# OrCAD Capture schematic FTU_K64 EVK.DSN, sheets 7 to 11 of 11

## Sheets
7 PAGE07  USB: size A4
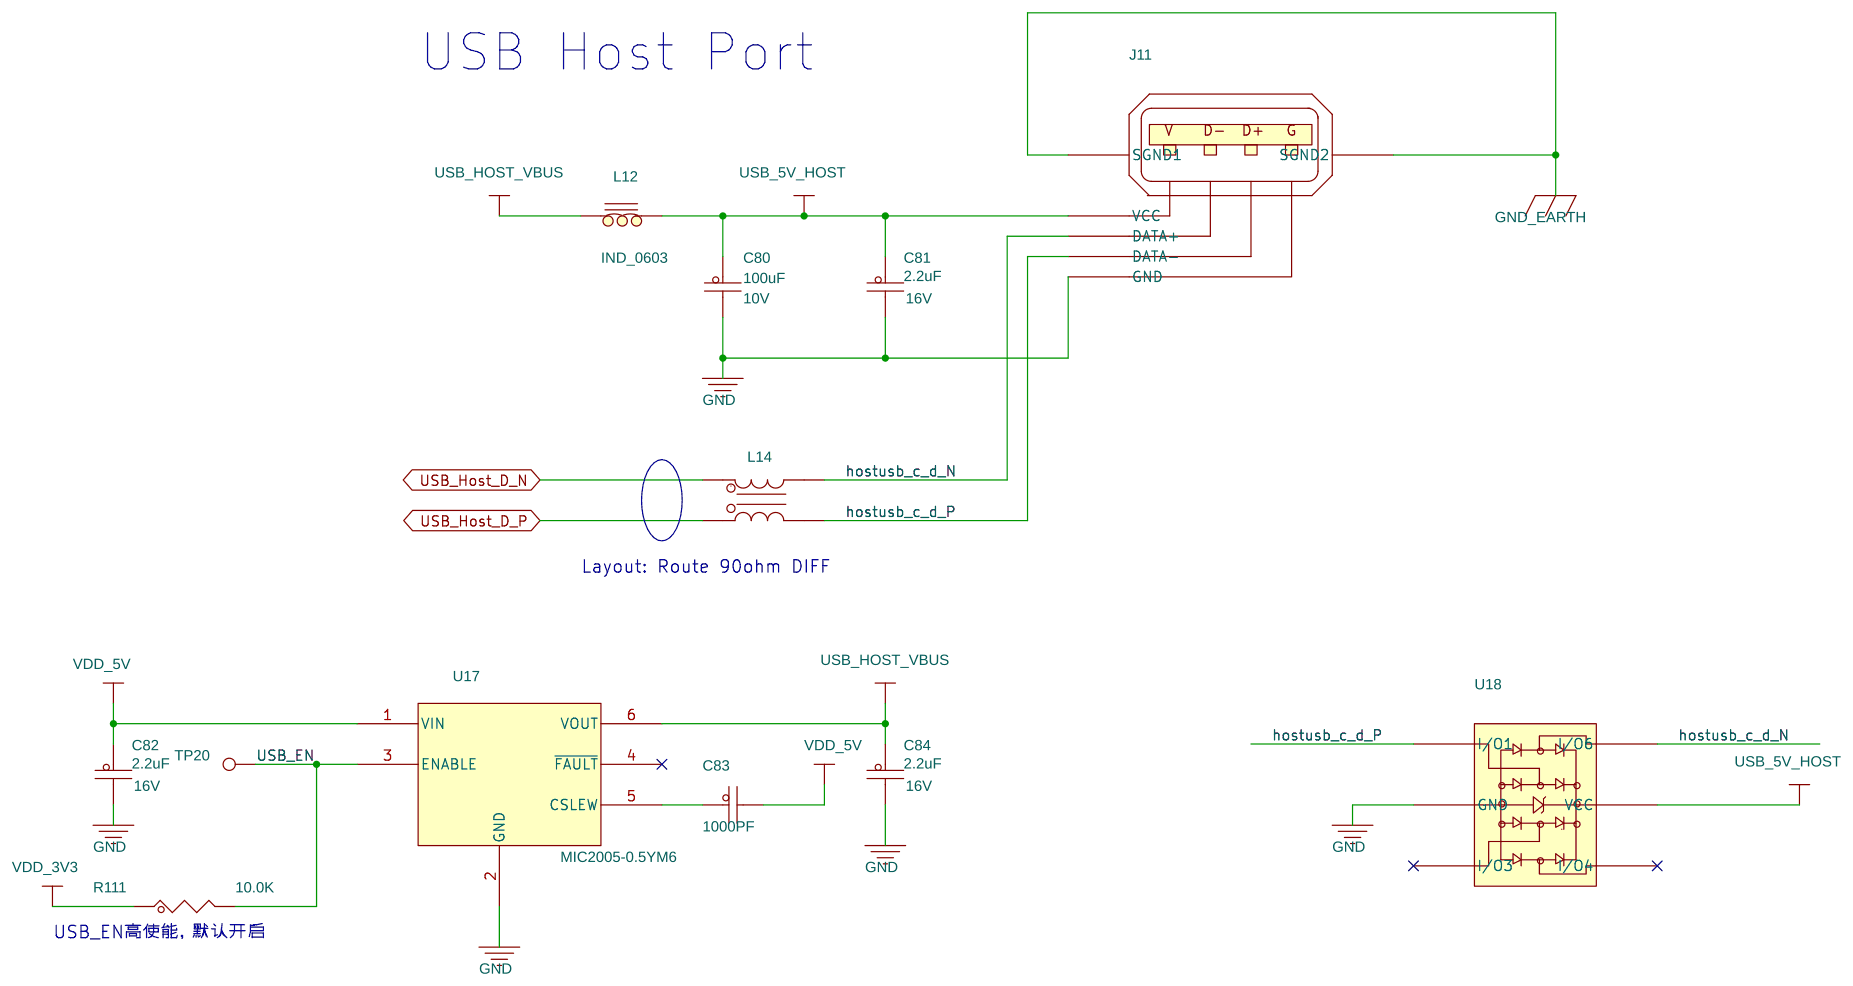
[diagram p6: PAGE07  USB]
8 PAGE08 RS485: size A3
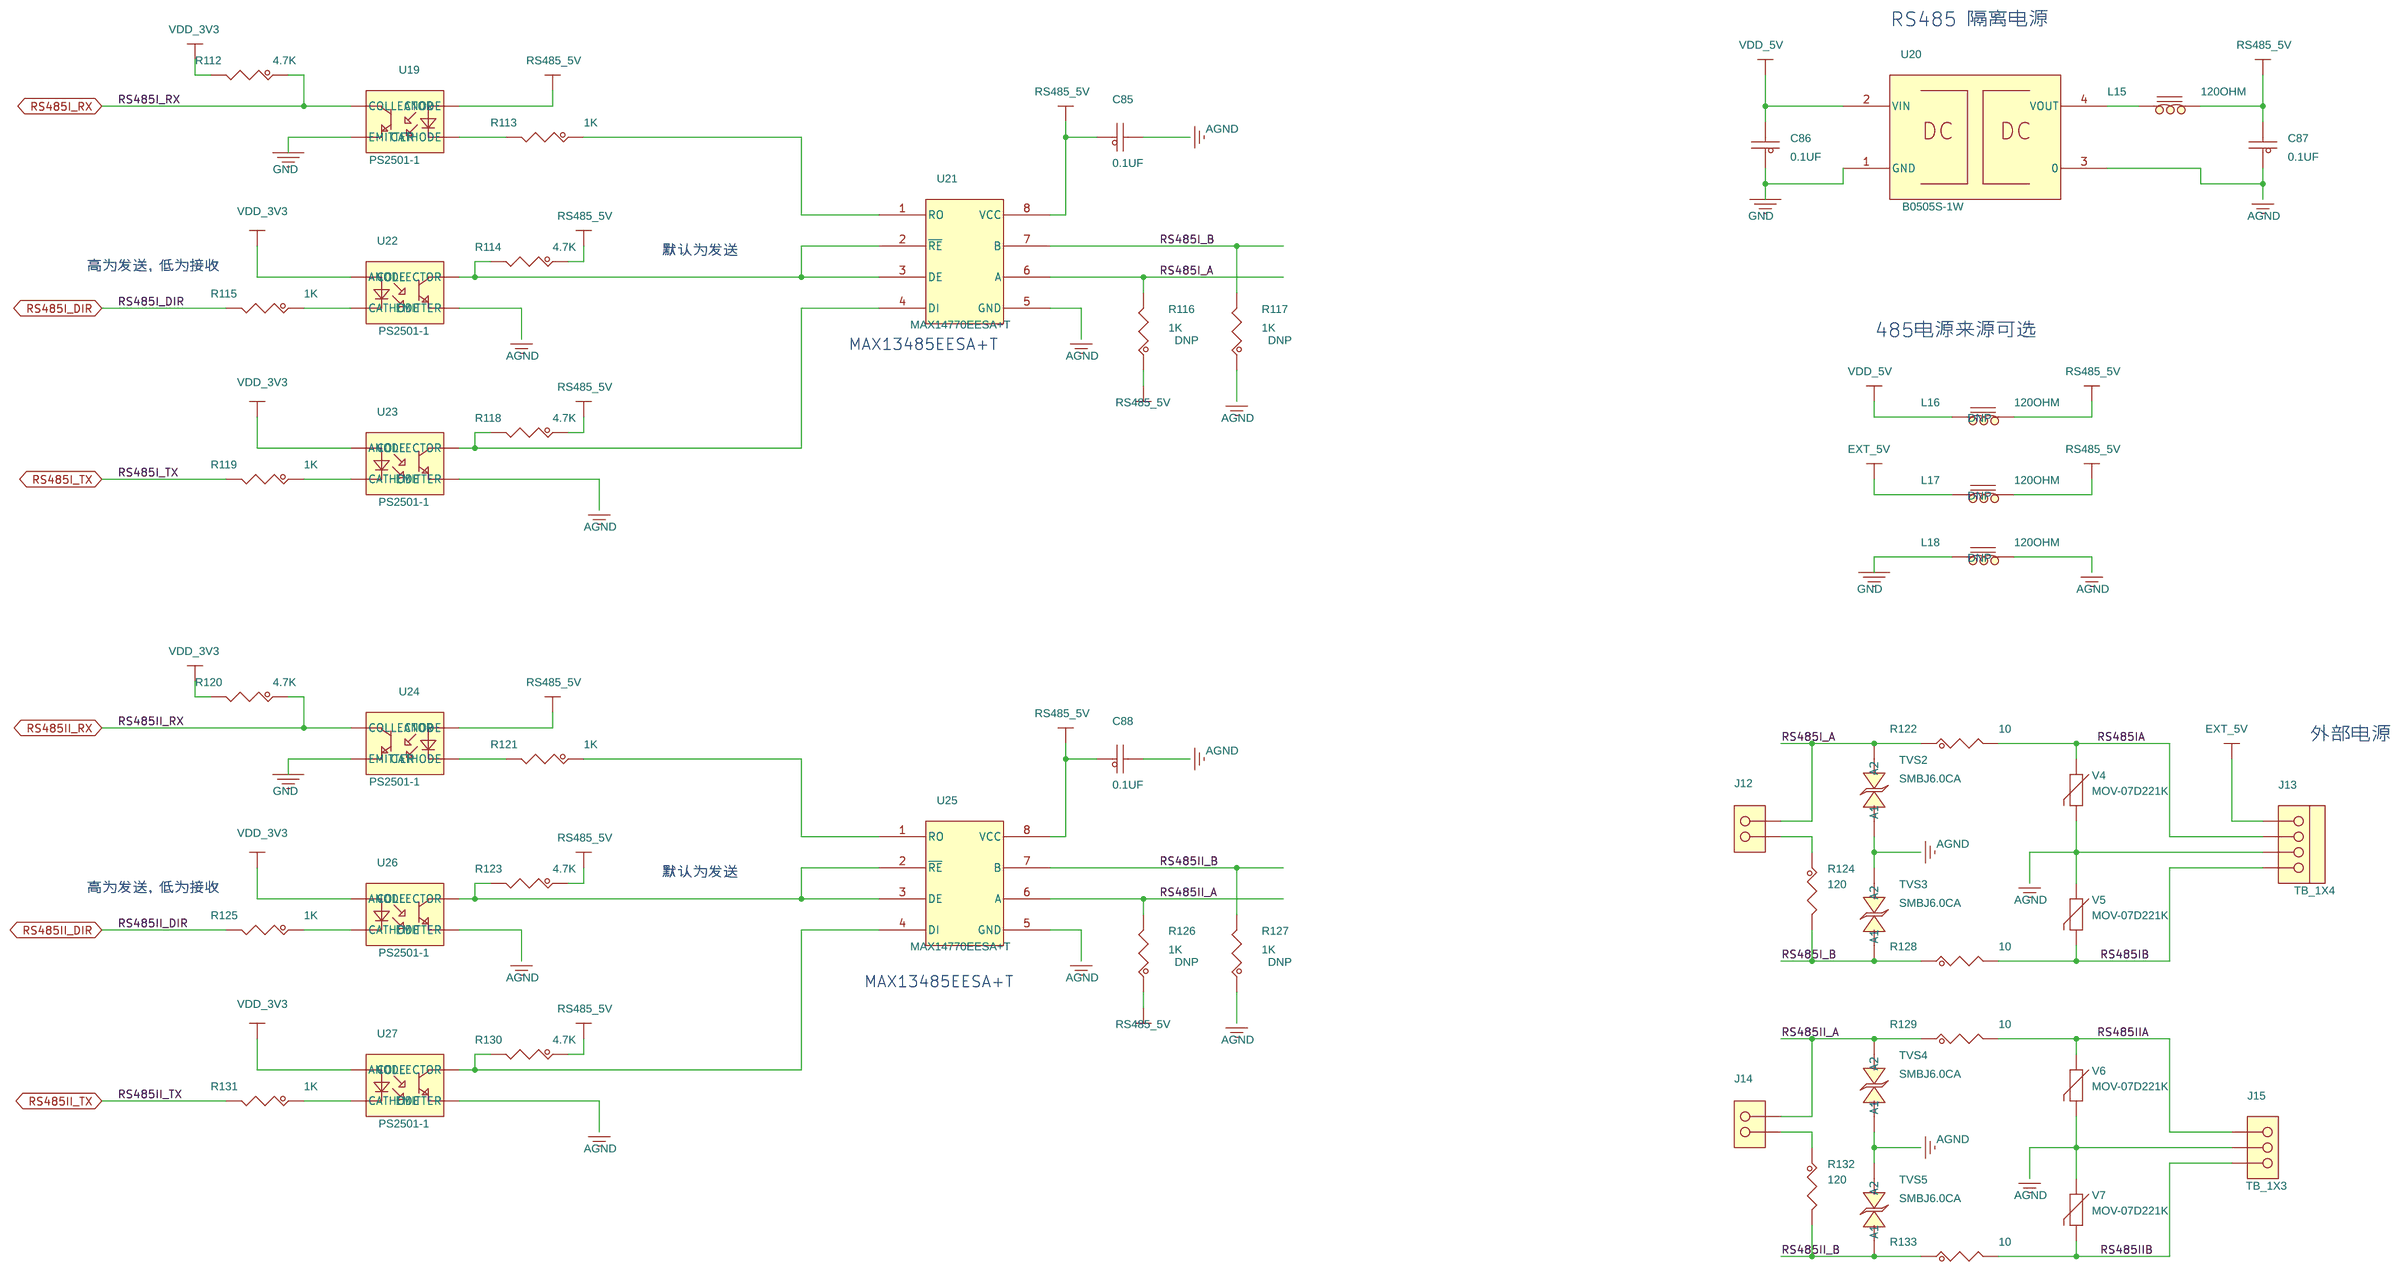
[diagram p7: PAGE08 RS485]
9 PAGE09 WDOG&Debug: size A3
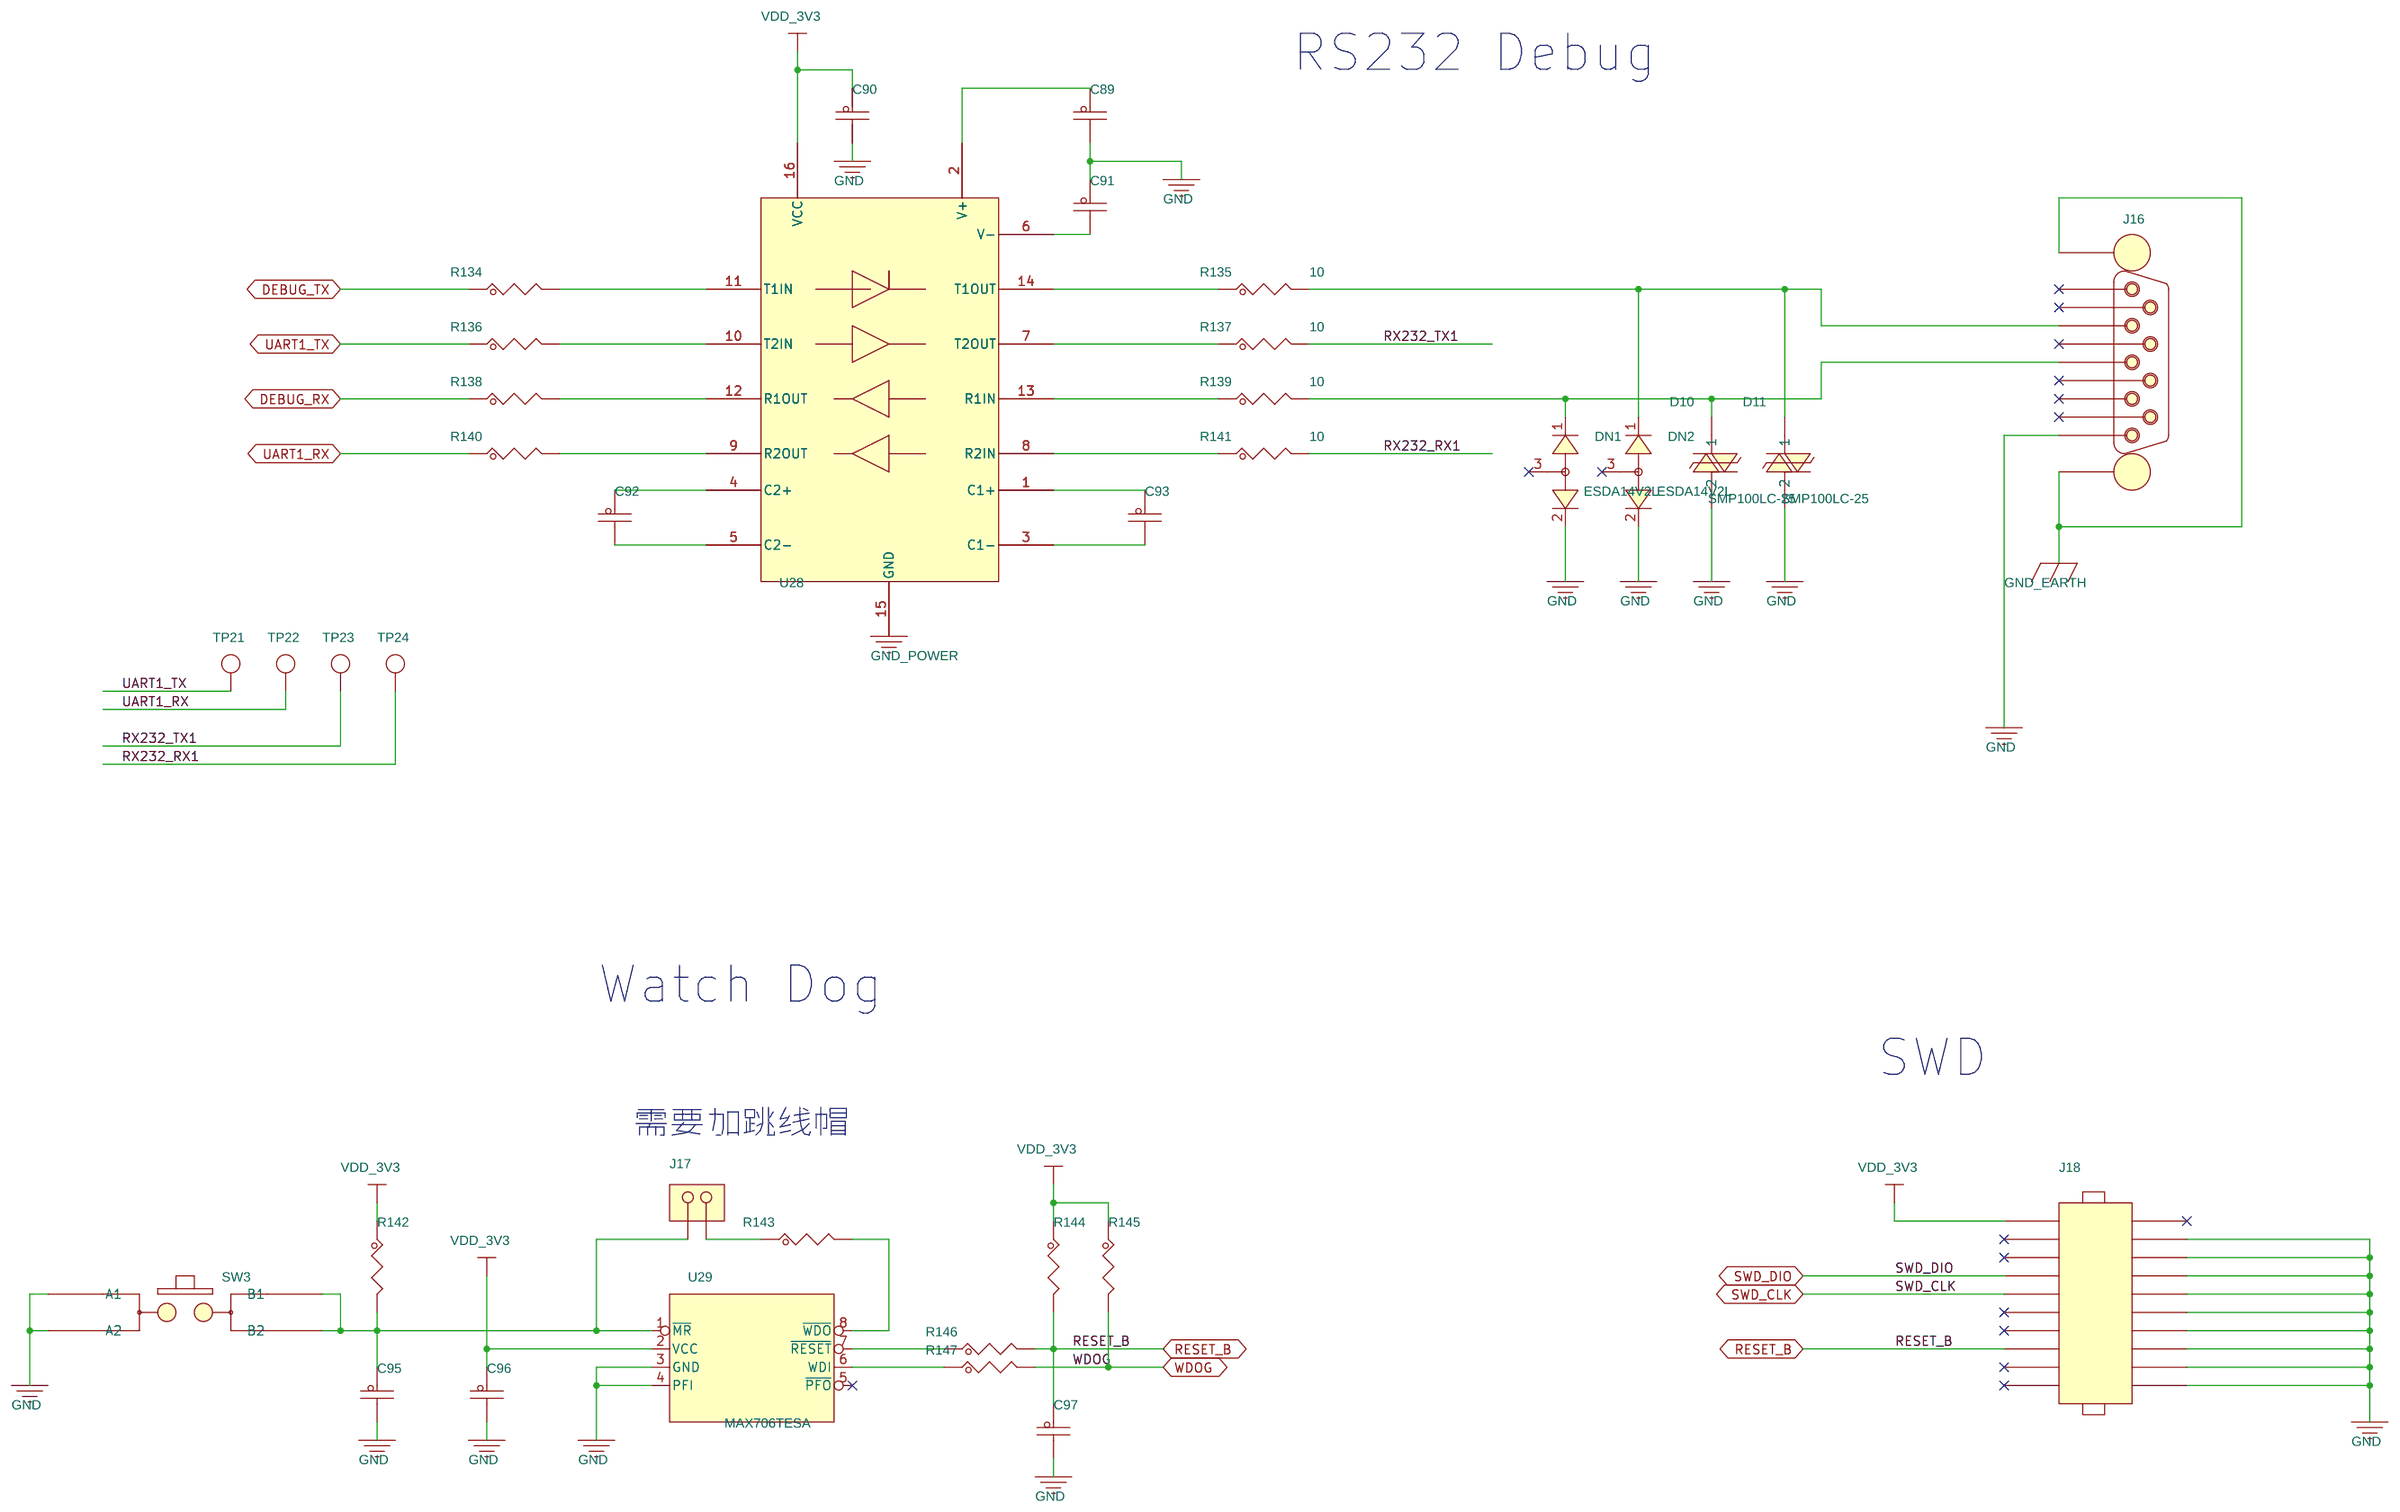
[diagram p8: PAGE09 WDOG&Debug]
10 PAGE10 GPRS&WIFI: size A4
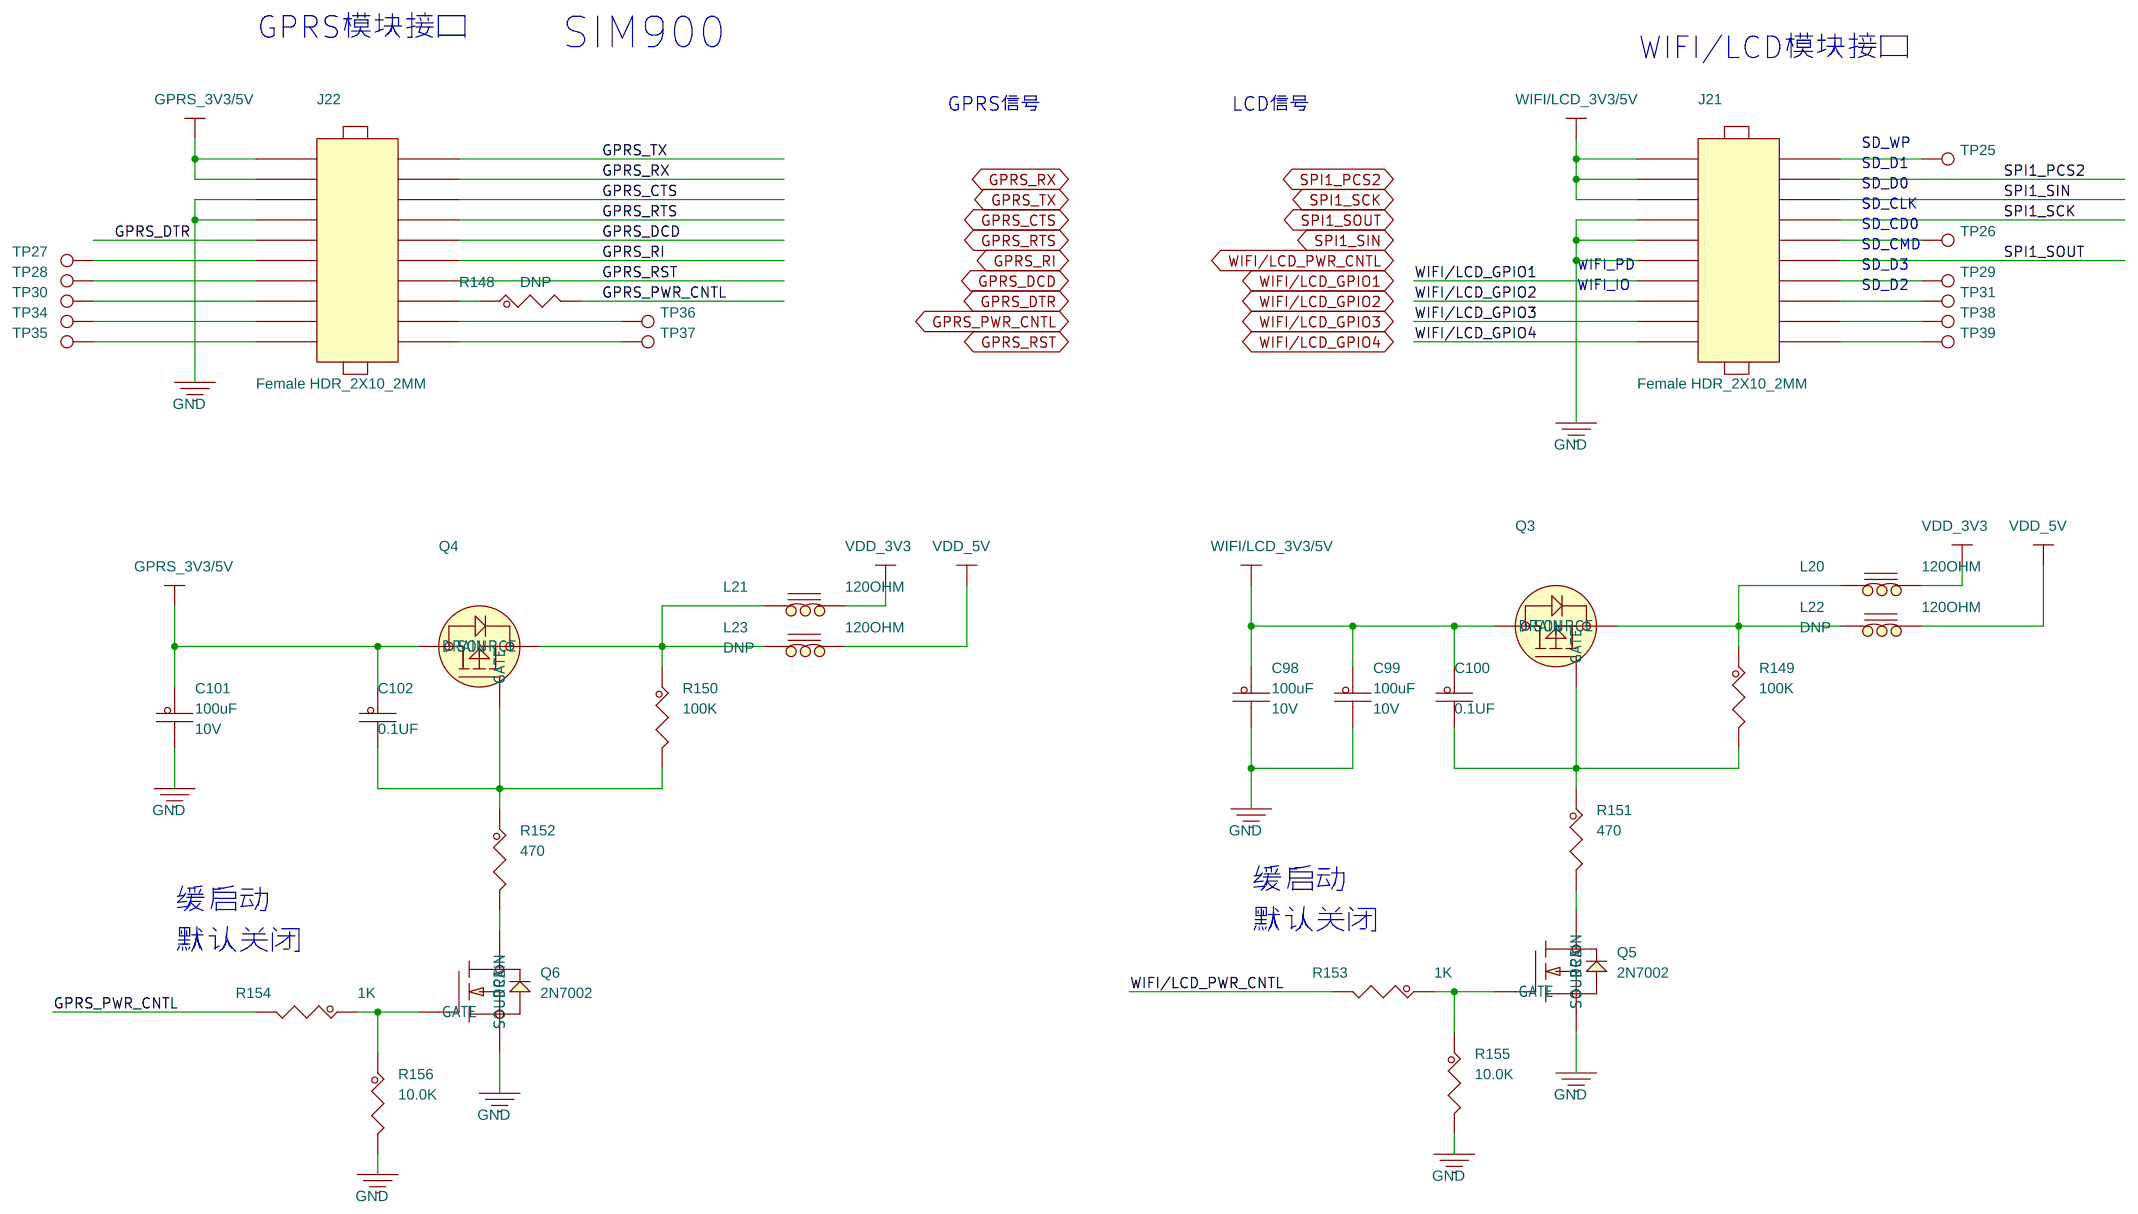
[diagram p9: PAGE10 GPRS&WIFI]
11 PAGE11 Power: size A4
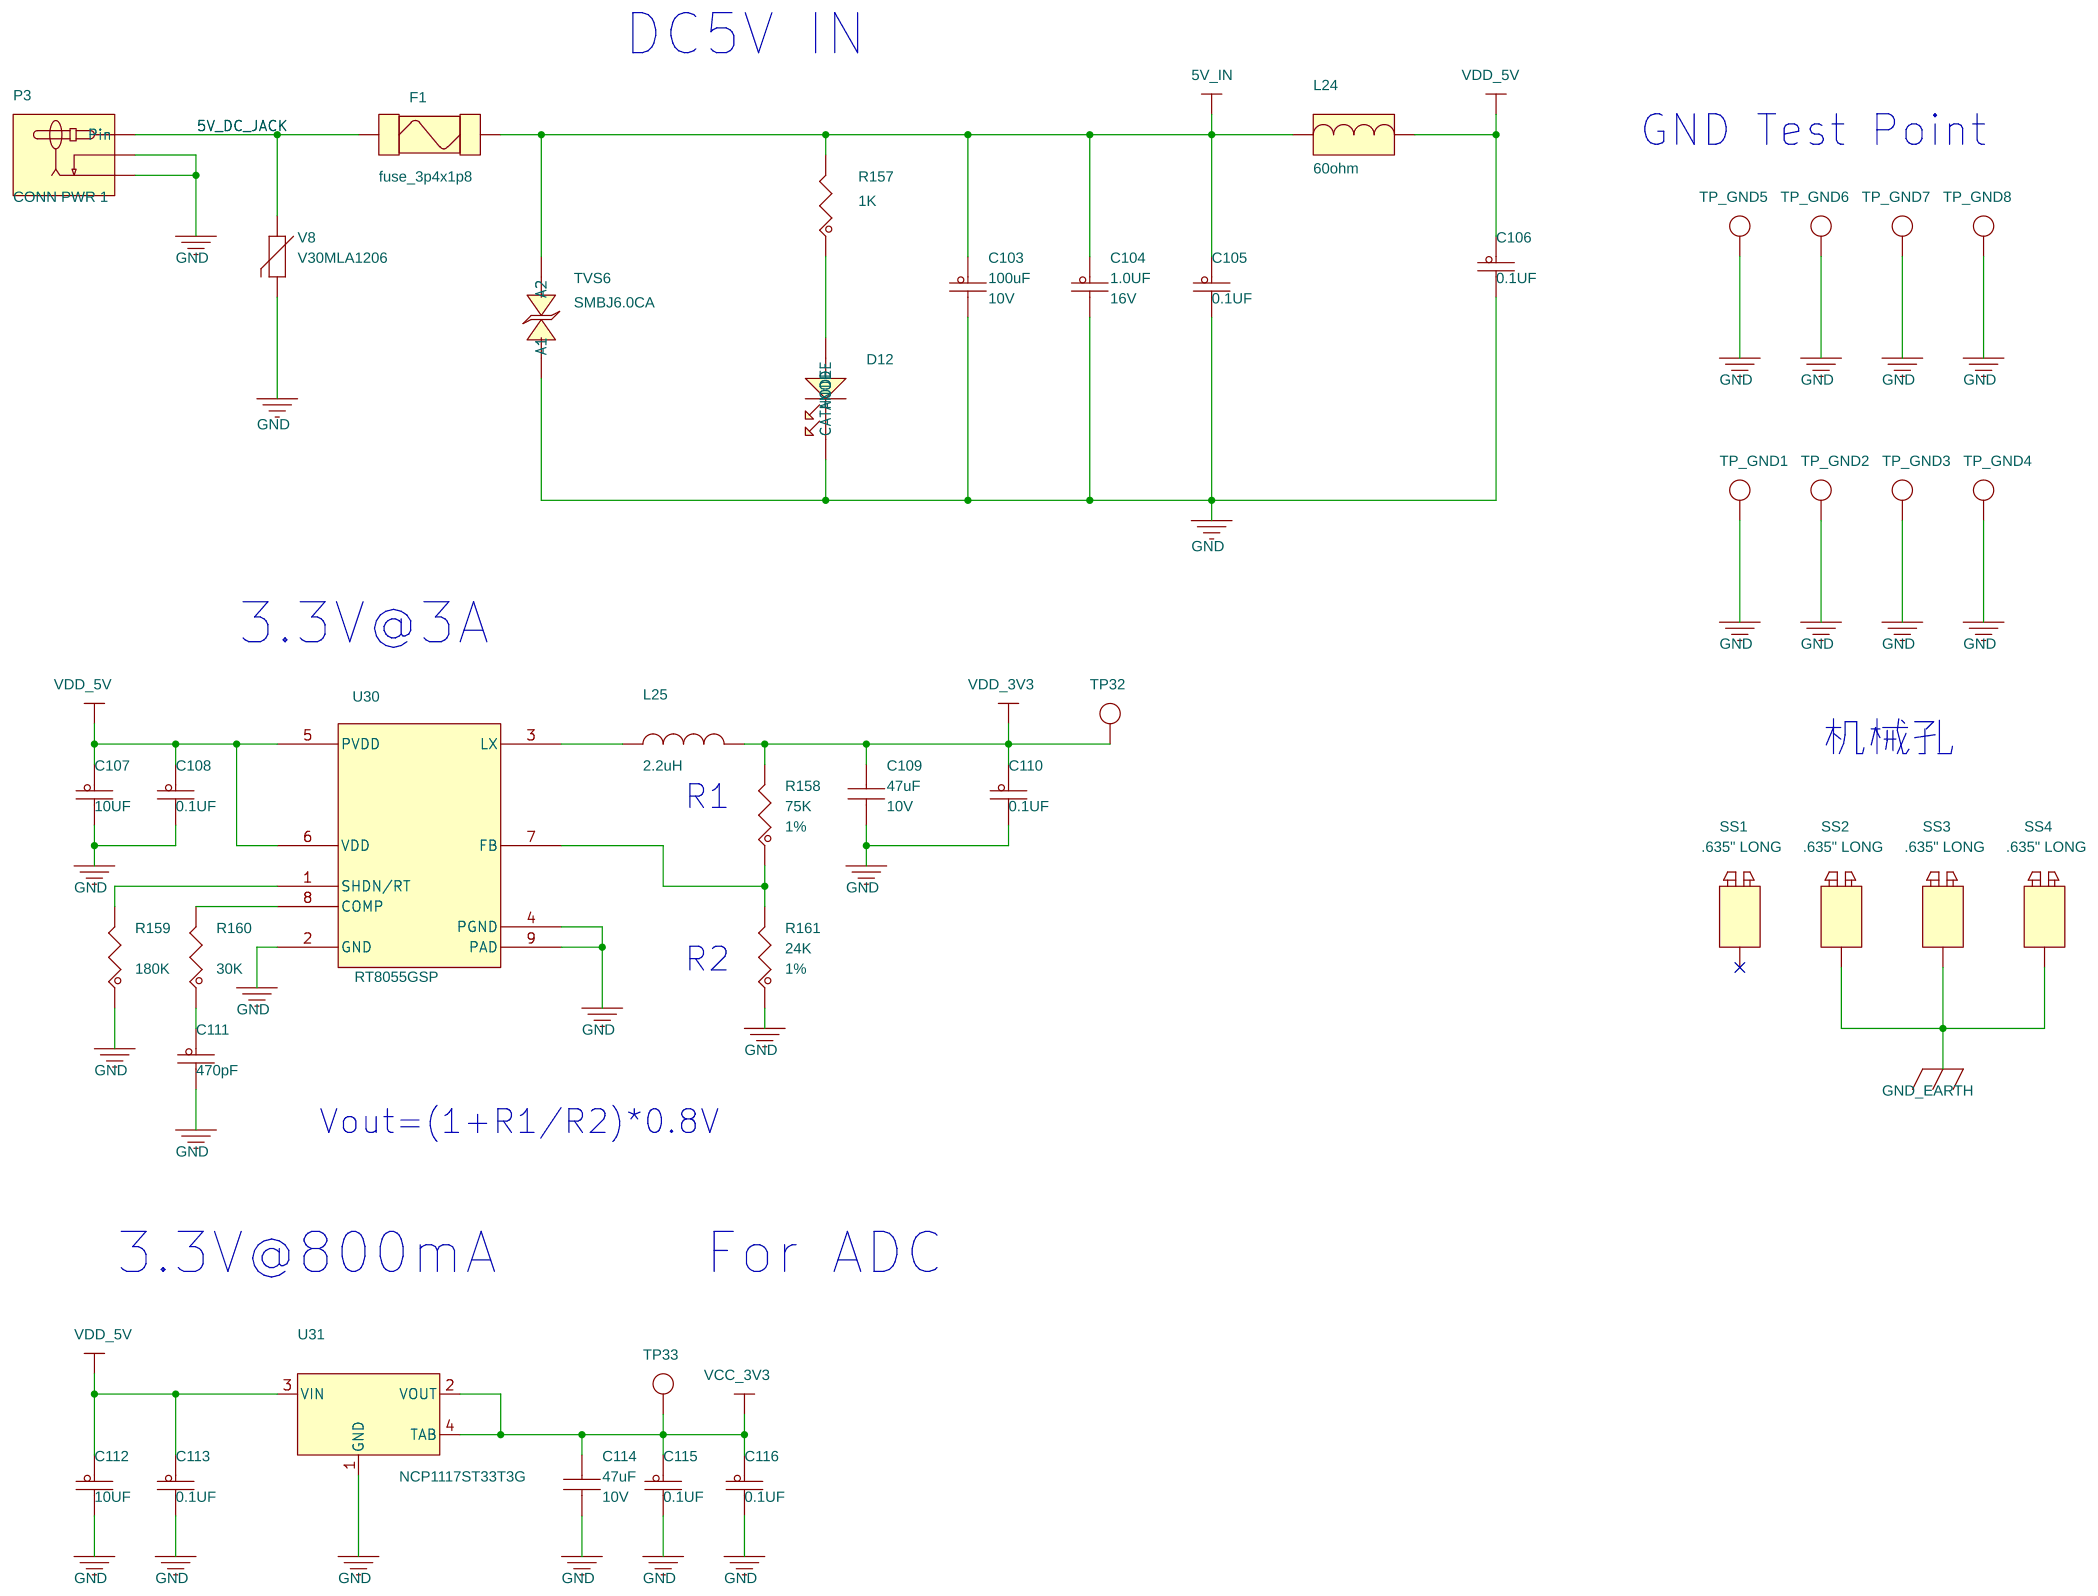
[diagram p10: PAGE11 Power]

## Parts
sheet PAGE07  USB
C80  100uF  [CC1206]
C81  2.2uF  [CC0603]
C82  2.2uF  [CC0603]
C83  1000PF  [CC0603]
C84  2.2uF  [CC0603]
J11  USB_TYPE_A  [USB_A]
L12  120OHM  [IND_0603]
L14  90OHM  [ind4_choke_0805]
R111  10.0K  [RC0603]
TP20  TEST POINT  [C035S]
U17  MIC2005-0.5YM6  [SOT23-6]
U18  SRV05-4  [SOT23-6]
sheet PAGE08 RS485
C85  0.1UF  [CC0603]
C86  0.1UF  [CC0603]
C87  0.1UF  [CC0603]
C88  0.1UF  [CC0603]
J12  HDR 1X2  [hdr102]
J13  TB_1X4  [con4_3p5_14p5x7mm]
J14  HDR 1X2  [hdr102]
J15  TB_1X3  [con3_3p5_11x7mm]
L15  120OHM  [IND_0603]
L16  120OHM  [IND_0603]
L17  120OHM  [IND_0603]
L18  120OHM  [IND_0603]
R112  4.7K  [RC0603]
R113  1K  [RC0603]
R114  4.7K  [RC0603]
R115  1K  [RC0603]
R116  1K  [RC0603]
R117  1K  [RC0603]
R118  4.7K  [RC0603]
R119  1K  [RC0603]
R120  4.7K  [RC0603]
R121  1K  [RC0603]
R122  10  [RC0805]
R123  4.7K  [RC0603]
R124  120  [RC0805]
R125  1K  [RC0603]
R126  1K  [RC0603]
R127  1K  [RC0603]
R128  10  [RC0805]
R129  10  [RC0805]
R130  4.7K  [RC0603]
R131  1K  [RC0603]
R132  120  [RC0805]
R133  10  [RC0805]
TVS2  SMBJ6.0CA  [do-214aa_bidir]
TVS3  SMBJ6.0CA  [do-214aa_bidir]
TVS4  SMBJ6.0CA  [do-214aa_bidir]
TVS5  SMBJ6.0CA  [do-214aa_bidir]
U19  PS2501-1  [4dip300]
U20  B0505S-1W  [B0505S-1W_SIP]
U21  MAX14770EESA+T  [so8_1p27_4x5]
U22  PS2501-1  [4dip300]
U23  PS2501-1  [4dip300]
U24  PS2501-1  [4dip300]
U25  MAX14770EESA+T  [so8_1p27_4x5]
U26  PS2501-1  [4dip300]
U27  PS2501-1  [4dip300]
V4  MOV-07D221K  [varistor_5_9x5p8_th]
V5  MOV-07D221K  [varistor_5_9x5p8_th]
V6  MOV-07D221K  [varistor_5_9x5p8_th]
V7  MOV-07D221K  [varistor_5_9x5p8_th]
sheet PAGE09 WDOG&Debug
C89  0.1UF  [CC0603]
C90  0.1UF  [CC0603]
C91  0.1UF  [CC0603]
C92  0.1UF  [CC0603]
C93  0.1UF  [CC0603]
C95  0.1UF  [CC0603]
C96  0.1UF  [CC0603]
C97  0.1UF  [CC0603]
D10  SMP100LC-25  [DO-214AA]
D11  SMP100LC-25  [DO-214AA]
DN1  ESDA14V2L  [SOT-23]
DN2  ESDA14V2L  [SOT-23]
J16  DB9  [CON_DB9S_RA_318]
J17  HDR 1X2  [hdr102]
J18  HDR 2X10  [HDR_2X10]
R134  0  [RC0603]
R135  10  [RC0805]
R136  0  [RC0603]
R137  10  [RC0805]
R138  0  [RC0603]
R139  10  [RC0805]
R140  0  [RC0603]
R141  10  [RC0805]
R142  10.0K  [RC0603]
R143  0  [RC0603]
R144  10.0K  [RC0603]
R145  10.0K  [RC0603]
R146  0  [RC0603]
R147  0  [RC0603]
SW3  SPST PB  [SW4_PB_ESW_SM_P177]
TP21  TPAD_040  [TPAD_040]
TP22  TPAD_040  [TPAD_040]
TP23  TPAD_040  [TPAD_040]
TP24  TPAD_040  [TPAD_040]
U28  SP3232  [SSOP16]
U29  MAX706TESA  [SO8_1P27_4X5]
sheet PAGE10 GPRS&WIFI
C98  100uF  [CC1206]
C99  100uF  [CC1206]
C100  0.1UF  [CC0603]
C101  100uF  [CC1206]
C102  0.1UF  [CC0603]
J21  Female HDR_2X10_2MM  [HDR210_2MM]
J22  Female HDR_2X10_2MM  [HDR210_2MM]
L20  120OHM  [IND_0603]
L21  120OHM  [IND_0603]
L22  120OHM  [IND_0603]
L23  120OHM  [IND_0603]
Q3  AO3415  [SOT-23]
Q4  AO3415  [SOT-23]
Q5  2N7002  [SOT-23]
Q6  2N7002  [SOT-23]
R148  0  [RC0603]
R149  100K  [RC0603]
R150  100K  [RC0603]
R151  470  [RC0603]
R152  470  [RC0603]
R153  1K  [RC0603]
R154  1K  [RC0603]
R155  10.0K  [RC0603]
R156  10.0K  [RC0603]
TP25  TEST POINT  [C035S]
TP26  TEST POINT  [C035S]
TP27  TEST POINT  [C035S]
TP28  TEST POINT  [C035S]
TP29  TEST POINT  [C035S]
TP30  TEST POINT  [C035S]
TP31  TEST POINT  [C035S]
TP34  TEST POINT  [C035S]
TP35  TEST POINT  [C035S]
TP36  TEST POINT  [C035S]
TP37  TEST POINT  [C035S]
TP38  TEST POINT  [C035S]
TP39  TEST POINT  [C035S]
sheet PAGE11 Power
C103  100uF  [CC1206]
C104  1.0UF  [CC0603]
C105  0.1UF  [CC0603]
C106  0.1UF  [CC0603]
C107  10UF  [CC0805]
C108  0.1UF  [CC0603]
C109  47uF  [CC1206]
C110  0.1UF  [CC0603]
C111  470pF  [CC0603]
C112  10UF  [CC0805]
C113  0.1UF  [CC0603]
C114  47uF  [CC1206]
C115  0.1UF  [CC0603]
C116  0.1UF  [CC0603]
D12  LED_GREEN  [LED_0603]
F1  5A/32V  [fuse_3p4x1p8]
L24  60ohm  [IND_0805]
L25  2.2uH  [ind2_6p3x6p3]
P3  CONN PWR 1  [PJ-202B]
R157  1K  [RC0603]
R158  75K  [RC0603]
R159  180K  [RC0603]
R160  30K  [RC0603]
R161  24K  [RC0603]
SS1  .635" LONG  [spacer_139t]
SS2  .635" LONG  [spacer_139t]
SS3  .635" LONG  [spacer_139t]
SS4  .635" LONG  [spacer_139t]
TP32  TPAD_040  [TPAD_040]
TP33  TPAD_040  [TPAD_040]
TP_GND1  TESTLOOP_BLACK  [tp_th_063]
TP_GND2  TESTLOOP_BLACK  [tp_th_063]
TP_GND3  TESTLOOP_BLACK  [tp_th_063]
TP_GND4  TESTLOOP_BLACK  [tp_th_063]
TP_GND5  TPAD_040  [TPAD_040]
TP_GND6  TPAD_040  [TPAD_040]
TP_GND7  TPAD_040  [TPAD_040]
TP_GND8  TPAD_040  [TPAD_040]
TVS6  SMBJ6.0CA  [do-214aa_bidir]
U30  RT8055GSP  [so8_1p27_4x5_tab]
U31  NCP1117ST33T3G  [sot223]
V8  V30MLA1206  [RC1206]

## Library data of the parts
C80 C98 C99 C101 C103 = CAP_NP: CAP CER 100uF 10V 20% X5R 1206; AGILE_PN: 150-78880; CAD_APPROVED: Yes; FPLIST: CC1206_OV,CC1206,1206_CC; HEIGHT: 1.9MM; MFG_NAME01: TDK; MFG_PN01: C3216X5R1A107M; ROHS: Yes; Tolerance: 20%; VOLTAGE: 10V; WVDC: 10V
C81 C82 C84 = CAP_NP: CAP CER 2.2UF 16V 10% X5R 0603; AGILE_PN: 150-75417; CAD_APPROVED: YES; FPLIST: CC0603_OV,CC0603,0603_CC; HEIGHT: 0.9 MM; MFG_NAME01: MURATA; MFG_PN01: GRM188R61C225KE15D; ROHS: Yes; Tolerance: 10%; VOLTAGE: 16V; voltage rating: 16V
C83 = CAP_NP: CAP CER 1000PF 50V 10% C0G 0603; AGILE_PN: 150-75921; CAD_APPROVED: Yes; FPLIST: CC0603_OV,CC0603,0603_CC; HEIGHT: 0.91MM; MFG_NAME01: AVX; MFG_PN01: 06035U102KAT2A; ROHS: Yes; Tolerance: 10%; VOLTAGE: 50V
J11 = USB_A: CON 1X4 USB_TYPE_A_FEMALE RA SHLD TH -- 276H AU; AGILE_PN: 210-30008; CAD_APPROVED: Yes; HEIGHT: 7.01MM; MFG_NAME01: TYCO ELECTRONICS; MFG_PN01: 292303-1; ROHS: Yes
L12 = BEAD_0: IND FER BEAD 120OHM@100MHZ 2A 25% 0603; AGILE_PN: 180-30008; CAD_APPROVED: Yes; FPLIST: IND_0603,0603_CC; HEIGHT: 0.95MM; MFG_NAME01: MURATA; MFG_PN01: BLM18PG121SH1; PART_TYPE: FERRITE; ROHS: Yes; Tolerance: 25%
L14 = DLW43: IND CHK 90 OHM@100MHZ 330MA 25% 0805; AGILE_PN: 180-76336; CAD_APPROVED: Yes; HEIGHT: 1MM; MFG_NAME01: MURATA; MFG_PN01: DLW21HN900SQ2L; PART_TYPE: CHOKE; ROHS: Yes; Tolerance: 25%
R111 R142 R144 R145 R155 R156 = RES: RES MF 10.0K 1/10W 1% 0603; AGILE_PN: 470-75422; CAD_APPROVED: Yes; FPLIST: RC0603_OV,RC0603,0603_CC; MFG_NAME01: KOA SPEER; MFG_PN01: RK73H1JTTD1002F; ROHS: Yes; Tolerance: 5%
TP20 TP25-TP31 TP34-TP39 = Test_pad: TEST POINT PAD 35 MIL SMT, NO PART TO ORDER; AGILE_PN: 280-75148; ASSY_OPT: DNP; CAD_APPROVED: Yes; HEIGHT: 0.1 MM; MFG_NAME01: NA; MFG_PN01: NA; ROHS: Yes
U17 = MIC2015-0.5YM6: IC LIN SW PWR 0.5A 2.5-5.5V SOT23-6; AGILE_PN: 315-78290; CAD_APPROVED: Yes; HEIGHT: 1.45 MM; MFG_NAME01: MICREL; ROHS: Yes
U18 = SRV05-4: DIODE TVS ARRAY 12A 5V 300W SOT23_S6; AGILE_PN: 480-75205; CAD_APPROVED: Yes; HEIGHT: 1.45mm; MFG_NAME01: SEMTECH CORP; MFG_PN01: SRV05-4.TCT; ROHS: Yes
C85-C88 C100 C102 C105 C106 C108 C110 C113 C115 C116 = CAP_NP: CAP CER 0.10UF 25V 10% X7R 0603; AGILE_PN: 150-75016; CAD_APPROVED: Yes; FPLIST: CC0603_OV,CC0603,0603_CC; HEIGHT: 0.97 MM; MFG_NAME01: KEMET; MFG_PN01: C0603C104K3RAC; ROHS: Yes; Tolerance: 10%; VOLTAGE: 25V
J12 J14 J17 = CONN_HDR_2X1: HDR 1X2 TH 100MIL SP 330H SN 120L; AGILE_PN: 210-79561; CAD_APPROVED: Yes; HEIGHT: 8.39MM; MFG_NAME01: FRAMATOME CONNECTORS INTERNATIONAL; MFG_PN01: 69190-402HLF; ROHS: Yes
J13 = CON_HDR_1X4: CON 1X4 TB TH 3.5MM SP 335H -- 138L; AGILE_PN: 210-80422; CAD_APPROVED: Yes; HEIGHT: 8.5MM; MFG_NAME01: Phoenix Contact; MFG_PN01: 1751264; ROHS: Yes
J15 = CONN_HDR_3X1: CON 1X3 TB TH 3.5MM SP 354H -- 118L; AGILE_PN: 210-80378; CAD_APPROVED: Yes; HEIGHT: 9MM; MFG_NAME01: Phoenix Contact; MFG_PN01: 1751251; ROHS: Yes
L15 L20 L21 = BEAD_0: IND FER BEAD 120OHM@100MHZ 2A 25% 0603; AGILE_PN: 180-30008; CAD_APPROVED: Yes; FPLIST: IND_0603,0603_CC; HEIGHT: 0.95MM; MFG_NAME01: MURATA; MFG_PN01: BLM18PG121SH1; PART_TYPE: FERRITE; PRIORITY_PN: 024-00067; ROHS: Yes; ROOM: RMII_PHY; Tolerance: 25%
L16-L18 L22 L23 = BEAD_0: IND FER BEAD 120OHM@100MHZ 2A 25% 0603; AGILE_PN: 180-30008; ASSY_OPT: DNP; CAD_APPROVED: Yes; FPLIST: IND_0603,0603_CC; HEIGHT: 0.95MM; MFG_NAME01: MURATA; MFG_PN01: BLM18PG121SH1; PART_TYPE: FERRITE; PRIORITY_PN: 024-00067; ROHS: Yes; ROOM: RMII_PHY; Tolerance: 25%
R112-R115 R118-R121 R123 R125 R130 R131 R153 R154 = RES: RES MF 10K 1/10W 5% 0603; AGILE_PN: 470-75410; CAD_APPROVED: Yes; FPLIST: RC0603_OV,RC0603,0603_CC; MFG_NAME01: KOA SPEER; MFG_PN01: RK73B1JTTD103J; ROHS: Yes; Tolerance: 5%
R116 R117 R126 R127 = RES: RES MF 10K 1/10W 5% 0603; AGILE_PN: 470-75410; ASSY_OPT: DNP; CAD_APPROVED: Yes; FPLIST: RC0603_OV,RC0603,0603_CC; MFG_NAME01: KOA SPEER; MFG_PN01: RK73B1JTTD103J; ROHS: Yes; Tolerance: 5%
R122 R128 R129 R133 = RES: RES MF 10 OHM 1/2W 5% 1210; AGILE_PN: 470-76662; CAD_APPROVED: Yes; FPLIST: RC1210,1210_CC; MFG_NAME01: KOA SPEER; MFG_PN01: RK73B2ETTE100J; ROHS: Yes; Tolerance: 5%
R124 R132 = RES: RES MF 120 OHM 1/8W 5% 0805; AGILE_PN: 470-30428; CAD_APPROVED: Yes; FPLIST: RC0805_OV,RC0805,0805_CC; MFG_NAME01: KOA SPEER; MFG_PN01: RK73B2ATTD121J; ROHS: Yes; Tolerance: 5%
TVS2 TVS5 = DIODE_TVS_BIDIR: DIODE TVS BIDIR 6.0V600W DO-214AB; AGILE_PN: 480-78509; CAD_APPROVED: Yes; HEIGHT: 2.62MM; MFG_NAME01: LITTELFUSE; ROHS: Yes
TVS3 TVS4 = DIODE_TVS_BIDIR: DIODE TVS BIDIR 13V 1500W DO-214AB; AGILE_PN: 480-78509; CAD_APPROVED: Yes; HEIGHT: 2.62MM; MFG_NAME01: LITTELFUSE; ROHS: Yes
U19 U22-U24 U26 U27 = PHOTOCOUPLER_4P: TRAN NPN PHOTOCOUPLER 80MA 80V DIP4; AGILE_PN: 480-78489; CAD_APPROVED: Yes; HEIGHT: 4.55MM; MFG_NAME01: CEL; ROHS: Yes
U20 = B0505S-1W: CLASS: IC; MFG_NAME01: MORNSUN
U21 = MAX13485: IC RS485 Transciever MAX14770EESA+T/SO8; CLASS: IC; MFG_NAME01: MAXIM; Part Number: S.01.67.01.0199
U25 = MAX13485: IC RS485 Transciever MAX14770EESA+T/SO8; MFG_NAME01: MAXIM; Part Number: S.01.67.01.0199
V4-V7 = VARISTOR: VARISTOR 140V 10% 0.25W RADIAL; AGILE_PN: 470-80124; CAD_APPROVED: Yes; MFG_NAME01: Bourns; ROHS: Yes
C89-C93 C95-C97 = CAP_NP: CAP CER 0.10UF 25V 10% X7R 0603; AGILE_PN: 150-75016; CAD_APPROVED: YES; FPLIST: CC0603_OV,CC0603,0603_CC; HEIGHT: 0.97 MM; MFG_NAME01: KEMET; MFG_PN01: C0603C104K3RAC; ROHS: Yes; Tolerance: 10%; VOLTAGE: 25V
D10 D11 = BTSS-2P_0: TVS; MFG_NAME01: ST
DN1 DN2 = ESDA14V2L: DUAL TRANSIL ARRAY TVS; MFG_NAME01: ST
J16 = CONN_DB9F_MTGTABS: CON 9 DB 0.318 SKT RA SHLD TH 54MIL SP 509H AU; AGILE_PN: 210-75755; CAD_APPROVED: Yes; HEIGHT: 12.92 MM; MFG_NAME01: TYCO ELECTRONICS; MFG_PN01: 5747844-4; ROHS: Yes
J18 = HDR_2X10: HDR 2X10 TH 100MIL CTR 363H AU; AGILE_PN: 210-75841; CAD_APPROVED: Yes; HEIGHT: 9.22MM; MFG_NAME01: TYCO ELECTRONICS; MFG_PN01: 1761602-7; ROHS: Yes
R134 R136 R138 R140 R143 R146 R147 = RES: RES MF ZERO OHM 1/10W -- 0603; AGILE_PN: 470-75407; CAD_APPROVED: Yes; FPLIST: RC0603_OV,RC0603,R603-X2,0603_CC; HEIGHT: 0.55 MM; MFG_NAME01: THYE MING TECH CO LTD; MFG_PN01: CR-03JL7----0R; ROHS: Yes; SIGNAL_MODEL: DEFAULT_RESISTOR_0.001OHM_2_1; Tolerance: 5%
R135 R137 R139 R141 = RES: RES MF 10.0 OHM 1/8W 1% 0805; AGILE_PN: 470-75903; CAD_APPROVED: Yes; FPLIST: RC0805_OV,RC0805,0805_CC; MFG_NAME01: BOURNS; MFG_PN01: CR0805-FX-10R0ELF; ROHS: Yes; Tolerance: 5%
SW3 = SW_PB_ESW: SW SPST MOM NO PB TACT 50mA 50V SMT; AGILE_PN: 510-77562; CAD_APPROVED: Yes; HEIGHT: 5MM; MFG_NAME01: E SWITCH; MFG_PN01: TL3301AF260QG/TR; ROHS: Yes
TP21-TP24 TP32 TP33 TP_GND5-TP_GND8 = TestLoop: TEST POINT PAD 40MIL DIA SMT, NO PART TO ORDER; AGILE_PN: 211-76643; CAD_APPROVED: Yes; HEIGHT: 0.1MM; MFG_NAME01: NOTACOMPONENT; MFG_PN01: NOTACOMPONENT; ROHS: Yes
U28 = SP3232E: IC XCVR RS232 120KBPS 3.0-5.5V SSOP16; AGILE_PN: 312-77064; CAD_APPROVED: Yes; HEIGHT: 1.99MM; MFG_NAME01: SIPEX; MFG_PN01: SP3232ECA-L; ROHS: Yes
U29 = ADM706_8P: IC VSUP MPU VOLTAGE MONITOR -- 1-5.5V SOIC8; AGILE_PN: 312-80124; CAD_APPROVED: Yes; HEIGHT: 1.75MM; MFG_NAME01: MAXIM; ROHS: Yes
J21 J22 = HDR_2X10: MFG_NAME01: PINREX ENTERPRISE CO., LTD
Q3 Q4 = MOSFET_P: TRAN PMOS PWR 12V 4.3A SOT23; AGILE_PN: 480-77718; CAD_APPROVED: Yes; HEIGHT: 1.12MM; MFG_NAME01: AOS; ROHS: Yes
Q5 Q6 = 2N7002: TRAN NMOS 60V 115MA SOT23; AGILE_PN: 480-75159; CAD_APPROVED: Yes; HEIGHT: 1.3MM; MFG_NAME01: ON SEMICONDUCTOR; MFG_PN01: 2N7002LT1G; ROHS: Yes
R148 = RES: RES MF ZERO OHM 1/10W -- 0603; AGILE_PN: 470-75407; ASSY_OPT: DNP; CAD_APPROVED: Yes; FPLIST: RC0603_OV,RC0603,R603-X2,0603_CC; HEIGHT: 0.55 MM; MFG_NAME01: THYE MING TECH CO LTD; MFG_PN01: CR-03JL7----0R; ROHS: Yes; SIGNAL_MODEL: DEFAULT_RESISTOR_0.001OHM_2_1; Tolerance: 5%
R149-R152 = RES: RES MF 470 OHM 1/10W 1% 0603; AGILE_PN: 470-30133; CAD_APPROVED: Yes; FPLIST: RC0603_OV,RC0603,0603_CC; MFG_NAME01: KOA SPEER; MFG_PN01: RK73H1JTTD4700F; ROHS: Yes; Tolerance: 5%
C104 = CAP_NP: CAP CER 1.0UF 16V 10% X7R 0603; AGILE_PN: 150-30124; CAD_APPROVED: Yes; FPLIST: CC0603_OV,CC0603,0603_CC; HEIGHT: 1.0MM; MFG_NAME01: AVX; MFG_PN01: 0603YC105KAT2A; ROHS: Yes; SIGNAL_MODEL: DEFAULT_CAPACITOR_1e+06pF_2_1; Tolerance: 10%; VOLTAGE: 16V; WVDC: 16V
C107 C112 = CAP_NP: CAP CER 10UF 16V 10% X5R 0805; AGILE_PN: 150-75283; CAD_APPROVED: Yes; FPLIST: CC0805_OV,CC0805,0805_CC; HEIGHT: 1.45MM; MFG_NAME01: AVX; MFG_PN01: 0805YD106KAT2A; ROHS: Yes; Tolerance: 10%; VOLTAGE: 16V
C109 C114 = MOT_CAP: CAP CER 47uF 10V 20% X5R 1206; AGILE_PN: 150-78578; CAD_APPROVED: Yes; FPLIST: CC1206_OV,CC1206,1206_CC; HEIGHT: 1.80MM; MFG_NAME01: TAIYO YUDEN; MFG_PN01: LMK316BJ476ML-T; ROHS: Yes; SIGNAL_MODEL: DEFAULT_CAPACITOR_4.7e+07pF_2_1; Tolerance: 20%; VOLTAGE: 10V; WVDC: 10V
C111 = CAP_NP: CAP CER 470PF 50V 10% C0G 0603; AGILE_PN: 150-75016; CAD_APPROVED: Yes; FPLIST: CC0603_OV,CC0603,0603_CC; HEIGHT: 0.97 MM; MFG_NAME01: KEMET; MFG_PN01: C0603C104K3RAC; ROHS: Yes; Tolerance: 10%; VOLTAGE: 25V
D12 = LED: LED ULTRA-BRIGHT GREEN SMT 0603; AGILE_PN: 370-75077; CAD_APPROVED: YES; HEIGHT: 0.8MM; MFG_NAME01: LITE ON; MFG_PN01: LTST-C190KGKT; ROHS: Yes
F1 = FUSE: FUSE FAST 5A 32V SMT; AGILE_PN: 510-77398; CAD_APPROVED: Yes; HEIGHT: 1.09MM; MFG_NAME01: COOPER BUSSMANN; MFG_PN01: 3216FF5-R; ROHS: Yes
L24 = BEAD: IND FER BEAD 60 OHM@100MHZ 3A 25%; AGILE_PN: 180-75019; CAD_APPROVED: Yes; HEIGHT: 1.05MM; MFG_NAME01: MURATA; MFG_PN01: BLM21PG600SN1B; PART_TYPE: FERRITE; ROHS: Yes; Tolerance: 25%
L25 = INDUCTOR: IND PWR 2.2UH@100KHZ 4.6A 30% SMT; AGILE_PN: 180-77798; CAD_APPROVED: Yes; HEIGHT: 4.5MM; MFG_NAME01: Shenzhen Sunlord Electronics Co., Ltd; MFG_PN01: SWPA6045S2R2NT; PART_TYPE: INDUCTOR\POWER; ROHS: Yes; Tolerance: 30%
P3 = DC_POWER_JACK: CON 1 PWR PLUG DIAM 2.0MM RA TH HIGH CURRENT-- 430H NI 140L; AGILE_PN: 210-79447; CAD_APPROVED: Yes; HEIGHT: 11.2MM; MFG_NAME01: CUI STACK; MFG_PN01: PJ-202AH; ROHS: Yes
R157 R158 R161 = RES: RES MF 100K 1/10W 1% 0603; AGILE_PN: 470-75424; CAD_APPROVED: Yes; FPLIST: RC0603_OV,RC0603,0603_CC; MFG_NAME01: KOA SPEER; MFG_PN01: RK73H1JTTD1003F; ROHS: Yes; Tolerance: 1%
R159 R160 = RES: RES MF 100K 1/10W 1% 0603; AGILE_PN: 470-75424; CAD_APPROVED: Yes; FPLIST: RC0603_OV,RC0603,0603_CC; MFG_NAME01: KOA SPEER; MFG_PN01: RK73H1JTTD1003F; ROHS: Yes; Tolerance: 5%
SS1-SS4 = SPACER: FASTENER, STANDOFF 4.5MMX3.53XM3.0X0.5 ROUND THR .635"L BRASS; AGILE_PN: 280-76498; CAD_APPROVED: Yes; HEIGHT: 16.13MM; MFG_NAME01: UNICORP; MFG_PN01: MSS251-R-1-A-16; ROHS: Yes
TP_GND1-TP_GND4 = TestLoop: TEST POINT PC MULTI PURPOSE BLK TH; AGILE_PN: 210-79450; CAD_APPROVED: Yes; HEIGHT: 8.13MM; MFG_NAME01: KEYSTONE ELECTRONICS; MFG_PN01: 5011; ROHS: Yes
TVS6 = DIODE_TVS_BIDIR: DIODE TVS BIDIR 13V 1500W DO-214AB; AGILE_PN: 480-78509; CAD_APPROVED: Yes; HEIGHT: 2.62MM; MFG_NAME01: LITTELFUSE; MFG_PN01: SMCJ13CA; ROHS: Yes
U30 = RT8011A_16_2: IC DCDC 2.6-5.5V 3A 2.6-5.5V SO8; AGILE_PN: 312-80098; CAD_APPROVED: Yes; HEIGHT: 0.8MM; MFG_NAME01: RICHTEK; ROHS: Yes
U31 = LD1117AS18: IC VREG LDO 1A 3.3V SOT223; AGILE_PN: 312-80039; CAD_APPROVED: Yes; HEIGHT: 1.8MM; MFG_NAME01: ON Semiconductor; ROHS: Yes
V8 = VARISTOR: VARISTOR 30V 10% 0.25W RADIAL; AGILE_PN: 470-80124; CAD_APPROVED: Yes; MFG_NAME01: LITTELFUSE; ROHS: Yes

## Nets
5V_DC_JACK: F1.1 P3.1(Pin) V8.1
5V_IN: C103.1 C104.1 C105.1 F1.2 L24.1 R157.2 TVS6.2(A2)
AGND: C85.2 C87.1 C88.2 J13.3 J15.2 L18.2 R117.1 R127.1 TVS2.1(A1) TVS3.2(A2) TVS4.1(A1) TVS5.2(A2) U20.3(0) U21.5(GND) U22.3(EMITTER) U23.3(EMITTER) U25.5(GND) U26.3(EMITTER) U27.3(EMITTER) V4.2 V5.1 V6.2 V7.1 ; also on sheet 6
GND: C80.2 C81.2 C82.2 C84.2 C86.1 C89.2 C90.2 C91.1 C95.2 C96.2 C97.2 C98.2 C99.2 C101.2 C103.2 C104.2 C105.2 C106.2 C107.2 C108.2 C109.2 C110.2 C111.2 C112.2 C113.2 C114.2 C115.2 C116.2 D10.C(2) D11.C(2) D12.C(CATHODE) DN1.2 DN2.2 J11.A4(GND) J16.5 J18.4 J18.6 J18.8 J18.10 J18.12 J18.14 J18.16 J18.18 J18.20 J21.7 J21.9 J21.11 J22.5 J22.7 L18.1 P3.2 P3.3 Q5.2(SOURCE) Q6.2(SOURCE) R155.2 R156.2 R159.1 R161.1 SW3.1(A1) SW3.2(A2) TP_GND1.1(Pin1) TP_GND2.1(Pin1) TP_GND3.1(Pin1) TP_GND4.1(Pin1) TP_GND5.1(Pin1) TP_GND6.1(Pin1) TP_GND7.1(Pin1) TP_GND8.1(Pin1) TVS6.1(A1) U17.2(GND) U18.2(GND) U19.3(EMITTER) U20.1(GND) U24.3(EMITTER) U28.15(GND) U29.3(GND) U29.4(PFI) U30.2(GND) U30.4(PGND) U30.9(PAD) U31.1(GND) V8.2 ; also on sheet 2 3 5 6
GND_EARTH: J11.S1(SGND1) J11.S2(SGND2) J16.M1 J16.M2 SS2.1(NC) SS3.1(NC) SS4.1(NC) ; also on sheet 5
GPRS_3V3/5V: C101.1 C102.1 J22.1 J22.3 Q4.3(DRAIN)
VCC_3V3: C114.1 C115.1 C116.1 TP33.1(Pin1) U31.2(VOUT) U31.4(TAB) ; also on sheet 2
VDD_3V3: C90.1 C96.1 C109.1 C110.1 J18.1 L20.2 L21.2 L25.2 R111.1 R112.2 R120.2 R142.1 R144.1 R145.1 R158.2 TP32.1(Pin1) U22.1(ANODE) U23.1(ANODE) U26.1(ANODE) U27.1(ANODE) U28.16(VCC) U29.2(VCC) ; also on sheet 2 3 5 6
VDD_5V: C82.1 C83.2 C86.2 C106.1 C107.1 C108.1 C112.1 C113.1 L16.1 L22.2 L23.2 L24.2 U17.1(VIN) U20.2(VIN) U30.5(PVDD) U30.6(VDD) U31.3(VIN) ; also on sheet 2
WIFI/LCD_3V3/5V: C98.1 C99.1 C100.1 J21.1 J21.3 J21.5 Q3.3(DRAIN)
DEBUG_RX (page PAGE09 WDOG&Debug): R138.1
DEBUG_TX (page PAGE09 WDOG&Debug): R134.1
EXT_5V: J13.1 L17.1
GPRS_CTS (page PAGE10 GPRS&WIFI): J22.6
GPRS_DCD (page PAGE10 GPRS&WIFI): J22.10
GPRS_DTR (page PAGE10 GPRS&WIFI): J22.9
GPRS_PWR_CNTL (page PAGE10 GPRS&WIFI): R148.2 R154.2
GPRS_RI (page PAGE10 GPRS&WIFI): J22.12
GPRS_RST (page PAGE10 GPRS&WIFI): J22.14
GPRS_RTS (page PAGE10 GPRS&WIFI): J22.8
GPRS_RX (page PAGE10 GPRS&WIFI): J22.4
GPRS_TX (page PAGE10 GPRS&WIFI): J22.2
hostusb_c_d_N: J11.A2(DATA+) L14.2 U18.6(I/O6)
hostusb_c_d_P: J11.A3(DATA-) L14.3 U18.1(I/O1)
RESET_B: C97.1 J18.15 R144.2 R146.2 ; also on sheet 2
RS485_5V: C85.1 C87.2 C88.1 L15.2 L16.2 L17.2 R114.1 R116.1 R118.1 R123.1 R126.1 R130.1 U19.1(ANODE) U21.8(VCC) U24.1(ANODE) U25.8(VCC) ; also on sheet 6
RS485I_A: J12.2 R116.2 R122.1 TVS2.2(A2) U21.6(A)
RS485I_B: R117.2 R124.2 R128.1 TVS3.1(A1) U21.7(B)
RS485I_DIR (page PAGE08 RS485): R115.2
RS485I_RX (page PAGE08 RS485): R112.1 U19.4(COLLECTOR)
RS485I_TX (page PAGE08 RS485): R119.2
RS485IA: J13.2 R122.2 V4.1
RS485IB: J13.4 R128.2 V5.2
RS485II_A: J14.2 R126.2 R129.1 TVS4.2(A2) U25.6(A)
RS485II_B: R127.2 R132.2 R133.1 TVS5.1(A1) U25.7(B)
RS485II_DIR (page PAGE08 RS485): R125.2
RS485II_RX (page PAGE08 RS485): R120.1 U24.4(COLLECTOR)
RS485II_TX (page PAGE08 RS485): R131.2
RS485IIA: J15.1 R129.2 V6.1
RS485IIB: J15.3 R133.2 V7.2
RX232_RX1: R141.2 TP24.1(Pin1)
RX232_TX1: R137.2 TP23.1(Pin1)
SPI1_PCS2 (page PAGE10 GPRS&WIFI): J21.4
SPI1_SCK (page PAGE10 GPRS&WIFI): J21.8
SPI1_SIN (page PAGE10 GPRS&WIFI): J21.6
SPI1_SOUT (page PAGE10 GPRS&WIFI): J21.12
SWD_CLK (page PAGE09 WDOG&Debug): J18.9
SWD_DIO (page PAGE09 WDOG&Debug): J18.7
UART1_RX (page PAGE09 WDOG&Debug): R140.1 TP22.1(Pin1)
UART1_TX (page PAGE09 WDOG&Debug): R136.1 TP21.1(Pin1)
USB_5V_HOST: C80.1 C81.1 J11.A1(VCC) L12.2 U18.5(VCC)
USB_EN: R111.2 TP20.1(Pin1) U17.3(ENABLE)
USB_Host_D_N: L14.1 ; also on sheet 2
USB_Host_D_P: L14.4 ; also on sheet 2
USB_HOST_VBUS: C84.1 L12.1 U17.6(VOUT)
WDOG (page PAGE09 WDOG&Debug): R145.2 R147.2
WIFI/LCD_GPIO1 (page PAGE10 GPRS&WIFI): J21.13
WIFI/LCD_GPIO2 (page PAGE10 GPRS&WIFI): J21.15
WIFI/LCD_GPIO3 (page PAGE10 GPRS&WIFI): J21.17
WIFI/LCD_GPIO4 (page PAGE10 GPRS&WIFI): J21.19
WIFI/LCD_PWR_CNTL (page PAGE10 GPRS&WIFI): R153.2
N16757442: D11.A(1) DN2.1 J16.2 R135.2
N16757516: D10.A(1) DN1.1 J16.3 R139.2
N16758787: C93.1 U28.1(C1+)
N16758791: C93.2 U28.3(C1-)
N16758795: C92.1 U28.4(C2+)
N16758815: C92.2 U28.5(C2-)
N16758819: C91.2 U28.6(V-)
N16758823: R135.1 U28.14(T1OUT)
N16758837: R134.2 U28.11(T1IN)
N16758843: R138.2 U28.12(R1OUT)
N16758849: C89.1 U28.2(V+)
N16758873: R139.1 U28.13(R1IN)
N16795804: D12.A(ANODE) R157.1
N16798051: C83.1 U17.5(CSLEW)
N16826797: R114.2 U21.2(~{RE}) U21.3(DE) U22.4(COLLECTOR)
N16826898: R118.2 U21.4(DI) U23.4(COLLECTOR)
N16826947: J12.1 R124.1
N16841183: J14.1 R132.1
N16842812: R115.1 U22.2(CATHODE)
N16843774: R119.1 U23.2(CATHODE)
N16843986: R113.2 U19.2(CATHODE)
N16846359: R113.1 U21.1(RO)
N16848477: R125.1 U26.2(CATHODE)
N16848509: R123.2 U25.2(~{RE}) U25.3(DE) U26.4(COLLECTOR)
N16848511: R131.1 U27.2(CATHODE)
N16848567: R130.2 U25.4(DI) U27.4(COLLECTOR)
N16848581: R121.2 U24.2(CATHODE)
N16848643: R121.1 U25.1(RO)
N16852593: R143.2 U29.8(~{WDO})
N16852608: C95.1 J17.1 R142.2 SW3.3(B1) SW3.4(B2) U29.1(~{MR})
N16852627: R146.1 U29.7(~{RESET})
N16852920: R147.1 U29.6(WDI)
N16871213: L20.1 L22.1 Q3.2(SOURCE) R149.1
N16871247: Q5.1(GATE) R153.1 R155.1
N16871250: C100.2 Q3.1(GATE) R149.2 R151.1
N16871668: Q5.3(DRAIN) R151.2
N16872241: Q6.1(GATE) R154.1 R156.1
N16872243: C102.2 Q4.1(GATE) R150.2 R152.1
N16872250: L21.1 L23.1 Q4.2(SOURCE) R150.1
N16872280: Q6.3(DRAIN) R152.2
N16877055: R159.2 U30.1(SHDN/RT)
N16877530: R160.2 U30.8(COMP)
N16877846: C111.1 R160.1
N16878286: L25.1 U30.3(LX)
N16878713: R158.1 R161.2 U30.7(FB)
N16964483: J17.2 R143.1
N16997663: R140.2 U28.9(R2OUT)
N16997666: R136.2 U28.10(T2IN)
N17002285: J22.11 TP27.1(Pin1)
N17002298: J22.13 TP28.1(Pin1)
N17002307: J22.15 TP30.1(Pin1)
N17012939: R137.1 U28.7(T2OUT)
N17012953: R141.1 U28.8(R2IN)
N17025356: L15.1 U20.4(VOUT)
N17041648: J21.16 TP31.1(Pin1)
N17041650: J21.14 TP29.1(Pin1)
N17041652: J21.10 TP26.1(Pin1)
N17041654: J21.2 TP25.1(Pin1)
N17042189: J22.16 R148.1
N17042264: J22.17 TP34.1(Pin1)
N17042273: J22.19 TP35.1(Pin1)
N17042288: J22.18 TP36.1(Pin1)
N17042303: J22.20 TP37.1(Pin1)
N17042405: J21.18 TP38.1(Pin1)
N17042414: J21.20 TP39.1(Pin1)

Not connected (* = marked no-connect by the designer): DN1 3*; DN2 3*; J16 1* 4* 6* 7* 8* 9*; J18 2* 3* 5* 11* 13* 17* 19*; SS1 1(NC)*; U17 4(~{FAULT})*; U18 3(I/O3)* 4(I/O4)*; U29 5(~{PFO})*

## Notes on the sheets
sheet 7
- USB Host Port
- Layout: Route 90ohm DIFF
- USB_EN高使能，默认开启
sheet 8
- RS485 隔离电源
- 默认为发送
- 高为发送，低为接收
- 485电源来源可选
- MAX13485EESA+T
- 外部电源
- 高为发送，低为接收
- 默认为发送
- MAX13485EESA+T
sheet 9
- RS232 Debug
- Watch Dog
- SWD
- 需要加跳线帽
sheet 10
- GPRS模块接口
- SIM900
- WIFI/LCD模块接口
- GPRS信号
- LCD信号
- SD_WP
- SD_D1
- SD_D0
- SD_CLK
- SD_CD0
- SD_CMD
- WIFI_PD
- SD_D3
- WIFI_IO
- SD_D2
- 缓启动
- 缓启动
- 默认关闭
- 默认关闭
sheet 11
- DC5V IN
- GND Test Point
- 3.3V@3A
- 机械孔
- R1
- R2
- Vout=(1+R1/R2)*0.8V
- 3.3V@800mA
- For ADC
